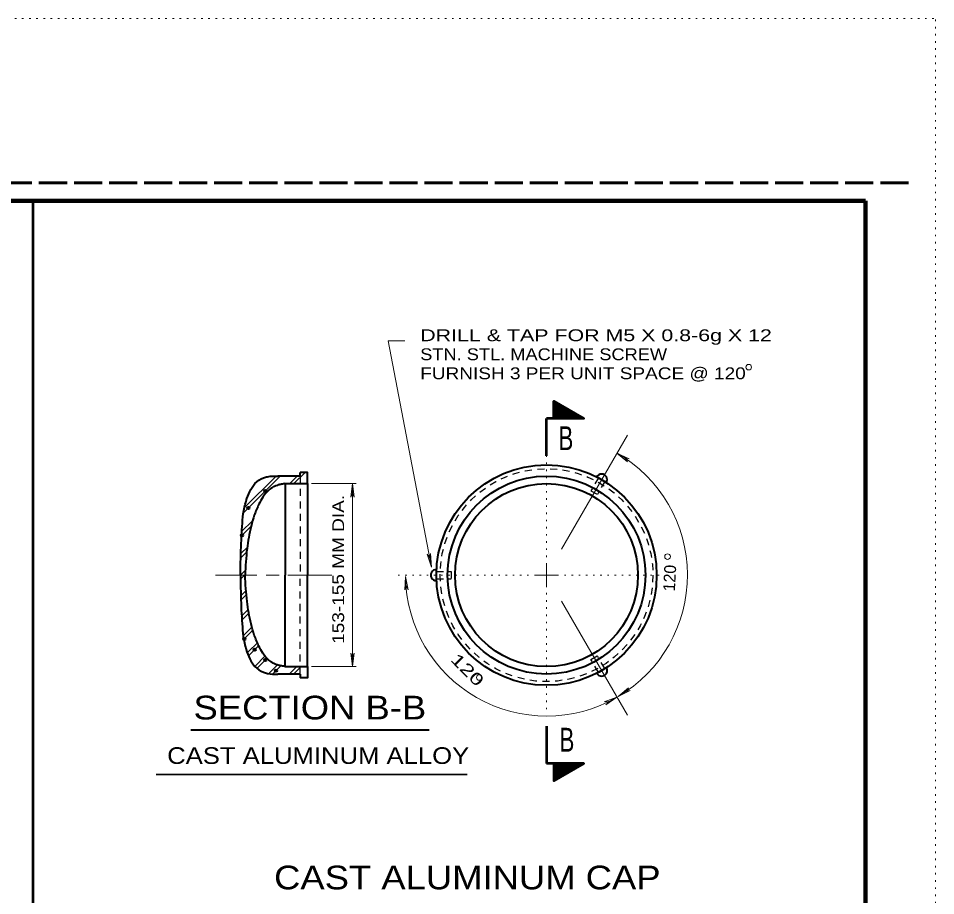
# Model space of a CAD drawing. Extents: x 312583 to 312854, y 144419 to 144597.
# Drawn here: x 312794.6 to 312853.5, y 144540.5 to 144596.8 of the extents above; entities that cross this region are included whole.
import ezdxf
from ezdxf.enums import TextEntityAlignment as Align

# ---------------------------------------------------------------- set-up
doc = ezdxf.new("R2010")
doc.units = 0
doc.header["$LTSCALE"] = 0.3
doc.header["$PDMODE"] = 32
doc.header["$PDSIZE"] = 0.15
for name, pattern in [('DOTTED', [1.5, 0.3, -1.2]), ('LONG_DASHED', [7.5, 6, -1.5]), ('SHORT_DASHED', [2.7, 1.5, -1.2])]:
    doc.linetypes.add(name, pattern=pattern)
for name, color, linetype, lineweight in [('1', 7, 'Continuous', 40), ('2', 7, 'Continuous', 13), ('62', 7, 'DOTTED', 13), ('63', 7, 'LONG_DASHED', 60)]:
    doc.layers.add(name, color=color, linetype=linetype, lineweight=lineweight)

msp = doc.modelspace()

# ---------------------------------------------------------------- linework, layer by layer
at = {"layer": '1', "lineweight": 158}
msp.add_line((312849, 144423.1446), (312849, 144585.0846), dxfattribs=at)
at = {"layer": '1', "lineweight": 13}
for p, q in [((312833.7137, 144570.0532), (312829.4971, 144562.7468)), ((312809.1267, 144565.1082), (312811.4344, 144567.4235)), ((312812.0401, 144566.9405), (312812.5231, 144567.4235)), ((312812.3084, 144566.9405), (312813.0291, 144567.6612)), ((312812.7147, 144567.6152), (312812.7607, 144567.6612)), ((312809.1651, 144565.4225), (312811.1277, 144567.3852)), ((312808.9581, 144563.8662), (312809.6481, 144564.5485)), ((312808.9504, 144563.5825), (312809.5791, 144564.2112)), ((312808.9197, 144562.4708), (312809.3031, 144562.8465)), ((312808.9121, 144562.1872), (312809.2571, 144562.5322)), ((312808.8814, 144561.0755), (312809.1957, 144561.3898)), ((312808.8891, 144560.8072), (312809.1804, 144561.1062)), ((312808.9044, 144559.7415), (312809.2417, 144560.0788)), ((312808.9121, 144559.4732), (312809.2647, 144559.8258)), ((312833.7137, 144552.0902), (312829.4971, 144559.3965)), ((312808.9351, 144558.4152), (312809.4027, 144558.8828)), ((312808.9504, 144558.1545), (312809.4411, 144558.6528)), ((312809.0577, 144557.1808), (312809.5944, 144557.7175)), ((312809.0807, 144556.9355), (312809.6634, 144557.5182)), ((312809.3721, 144556.1458), (312809.9701, 144556.7362)), ((312809.4641, 144555.9618), (312810.0467, 144556.5445)), ((312809.8167, 144555.2335), (312810.4761, 144555.8928)), ((312809.9394, 144555.0802), (312810.6141, 144555.7625)), ((312810.7137, 144554.7735), (312811.2811, 144555.3408)), ((312810.9744, 144554.7658), (312811.4957, 144555.2795)), ((312812.0324, 144554.7352), (312812.5001, 144555.2028)), ((312812.3007, 144554.7352), (312812.7684, 144555.2028)), ((312813.1364, 144554.4822), (312813.1901, 144554.5435))]:
    msp.add_line(p, q, dxfattribs=at)
at = {"layer": '1'}
for p, q in [((312812.7147, 144567.4235), (312811.2734, 144567.4235)), ((312812.7147, 144567.4235), (312812.7147, 144567.6612)), ((312811.7564, 144566.9405), (312811.7564, 144561.0755)), ((312813.1901, 144566.9405), (312813.1901, 144561.0755)), ((312831.7511, 144567.3698), (312832.3721, 144567.0172)), ((312811.7564, 144555.2028), (312811.7564, 144561.0755)), ((312813.1901, 144555.2028), (312813.1901, 144561.0755)), ((312821.4547, 144560.7152), (312821.4547, 144561.4282)), ((312832.3721, 144555.1338), (312831.7511, 144554.7735)), ((312812.7147, 144554.7198), (312811.2734, 144554.7198)), ((312812.7147, 144554.7198), (312812.7147, 144554.4822))]:
    msp.add_line(p, q, dxfattribs=at)
at = {"layer": '1', "linetype": 'SHORT_DASHED', "lineweight": 25}
for p, q in [((312812.7147, 144567.4235), (312812.7147, 144561.0755)), ((312831.8507, 144567.3162), (312831.3754, 144566.4805)), ((312832.2647, 144567.0785), (312831.7894, 144566.2428)), ((312831.7894, 144566.2428), (312831.3754, 144566.4805)), ((312812.7147, 144554.7198), (312812.7147, 144561.0755)), ((312821.4547, 144561.3132), (312822.4131, 144561.3132)), ((312822.4131, 144561.3132), (312822.4131, 144560.8302)), ((312821.4547, 144560.8302), (312822.4131, 144560.8302)), ((312831.3754, 144555.6628), (312831.7894, 144555.9005)), ((312831.8584, 144554.8348), (312831.3754, 144555.6628)), ((312832.2647, 144555.0725), (312831.7894, 144555.9005))]:
    msp.add_line(p, q, dxfattribs=at)
at = {"layer": '1', "lineweight": 158}
msp.add_lwpolyline([(312616.5, 144423.1446), (312616.5, 144585.0846), (312849, 144585.0846)], dxfattribs=at)
at = {"layer": '1', "lineweight": 53}
msp.add_lwpolyline([(312849, 144468.4167), (312795.5728, 144468.4167), (312795.5728, 144585.0846)], dxfattribs=at)
at = {"layer": '1'}
for points in [[(312811.7564, 144566.9405), (312813.1901, 144566.9405), (312813.1901, 144567.6612), (312812.7147, 144567.6612)], [(312811.7564, 144555.2028), (312813.1901, 144555.2028), (312813.1901, 144554.4822), (312812.7147, 144554.4822)]]:
    msp.add_lwpolyline(points, dxfattribs=at)
for radius in [7.0687, 6.3499, 5.8708]:
    msp.add_circle((312828.5253, 144561.0717), radius, dxfattribs=at)
at = {"layer": '1', "linetype": 'SHORT_DASHED', "lineweight": 25}
msp.add_circle((312828.5253, 144561.0717), 6.8291, dxfattribs=at)
at = {"layer": '1'}
for centre, start, end in [((312832.0603, 144567.1964), 329.52448, 150.47552), ((312821.4537, 144561.0707), 89.52448, 270.47552), ((312832.062, 144554.9479), 209.52448, 30.47552)]:
    msp.add_arc(centre, 0.3575, start, end, dxfattribs=at)
for points in [[(312808.8814, 144561.0755), (312808.9044, 144562.4325), (312808.9887, 144564.1882), (312809.0654, 144565.0085), (312809.2494, 144565.8365), (312809.4871, 144566.4345), (312809.8091, 144566.9405), (312810.3611, 144567.3085), (312810.6217, 144567.3852), (312811.2734, 144567.4235)], [(312811.7564, 144566.9405), (312811.5264, 144566.9022), (312811.3117, 144566.8562), (312810.9897, 144566.7258), (312810.6984, 144566.5188), (312810.3151, 144566.0818), (312810.0697, 144565.6218), (312809.7707, 144564.9242), (312809.5714, 144564.1958), (312809.4104, 144563.4828), (312809.3031, 144562.7698), (312809.1804, 144561.0602)], [(312808.8814, 144561.0755), (312808.9044, 144559.7108), (312808.9887, 144557.9552), (312809.0654, 144557.1425), (312809.2494, 144556.3068), (312809.4871, 144555.7088), (312809.8091, 144555.2105), (312810.3611, 144554.8425), (312810.6217, 144554.7658), (312811.2734, 144554.7198)], [(312811.7564, 144555.2028), (312811.5264, 144555.2488), (312811.3117, 144555.2872), (312810.9897, 144555.4175), (312810.6984, 144555.6245), (312810.3151, 144556.0615), (312810.0697, 144556.5215), (312809.7707, 144557.2192), (312809.5714, 144557.9475), (312809.4104, 144558.6605), (312809.3031, 144559.3812), (312809.1804, 144561.0602)]]:
    msp.add_spline(points, degree=3, dxfattribs=at)
for p in [(312810.4761, 144566.4652), (312809.3951, 144565.3765), (312808.9887, 144563.6208), (312809.1267, 144556.9738), (312809.8014, 144556.2992), (312810.4761, 144555.6245), (312811.1584, 144554.9422)]:
    msp.add_point(p, dxfattribs=at)
at = {"layer": '2'}
for p, q in [((312819.4231, 144576.1022), (312818.3574, 144576.1022)), ((312821.1404, 144561.5892), (312818.3574, 144576.1022)), ((312833.0467, 144568.9032), (312833.7214, 144568.3435)), ((312833.0467, 144568.9032), (312833.8364, 144568.5275)), ((312833.7214, 144568.3435), (312833.5451, 144568.5888)), ((312833.8364, 144568.5275), (312833.5451, 144568.5888)), ((312813.4354, 144566.9405), (312816.3104, 144566.9405)), ((312816.0651, 144566.9405), (312815.9577, 144566.0742)), ((312816.0651, 144555.2028), (312816.0651, 144566.9405)), ((312816.0651, 144566.9405), (312816.1724, 144566.0742)), ((312815.9577, 144566.0742), (312816.0651, 144566.3502)), ((312816.1724, 144566.0742), (312816.0651, 144566.3502)), ((312820.8721, 144562.4248), (312821.0254, 144562.1718)), ((312821.1404, 144561.5892), (312820.8721, 144562.4248)), ((312821.0791, 144562.4632), (312821.0254, 144562.1718)), ((312821.1404, 144561.5892), (312821.0791, 144562.4632)), ((312828.5234, 144561.0755), (312828.5234, 144561.8422)), ((312807.2791, 144561.0755), (312809.9317, 144561.0755)), ((312810.5221, 144561.0755), (312811.3731, 144561.0755)), ((312811.9327, 144561.0755), (312814.7387, 144561.0755)), ((312819.4844, 144560.9912), (312819.4307, 144560.1172)), ((312819.4844, 144560.9912), (312819.6377, 144560.1325)), ((312828.5234, 144561.0755), (312827.7567, 144561.0755)), ((312828.5234, 144561.0755), (312827.7567, 144561.0755)), ((312828.5234, 144561.0755), (312828.5234, 144560.3088)), ((312828.5234, 144561.0755), (312829.2901, 144561.0755)), ((312819.4307, 144560.1172), (312819.5151, 144560.4008)), ((312819.6377, 144560.1325), (312819.5151, 144560.4008)), ((312815.9577, 144556.0692), (312816.0651, 144555.7932)), ((312816.0651, 144555.2028), (312815.9577, 144556.0692)), ((312816.1724, 144556.0692), (312816.0651, 144555.7932)), ((312816.0651, 144555.2028), (312816.1724, 144556.0692)), ((312813.4354, 144555.2028), (312816.3104, 144555.2028)), ((312833.1157, 144553.2785), (312833.7827, 144553.8458)), ((312833.1157, 144553.2785), (312833.8977, 144553.6695)), ((312833.7827, 144553.8458), (312833.6141, 144553.6082)), ((312833.8977, 144553.6695), (312833.6141, 144553.6082)), ((312833.0467, 144553.2402), (312832.2264, 144552.9335)), ((312832.2264, 144552.9335), (312832.5254, 144552.9718)), ((312833.0467, 144553.2402), (312832.3261, 144552.7495)), ((312832.3261, 144552.7495), (312832.5254, 144552.9718))]:
    msp.add_line(p, q, dxfattribs=at)
at = {"layer": '2', "lineweight": 35}
for p, q in [((312828.9987, 144572.1998), (312829.0141, 144572.2152)), ((312828.9987, 144572.1538), (312829.0371, 144572.2075)), ((312828.9987, 144572.1002), (312829.0524, 144572.1922)), ((312828.9987, 144572.0542), (312829.0754, 144572.1768)), ((312828.9987, 144572.0005), (312829.0984, 144572.1692)), ((312828.9987, 144571.9622), (312829.1137, 144572.1538)), ((312828.9987, 144571.9085), (312829.1367, 144572.1462)), ((312828.9987, 144571.8625), (312829.1597, 144572.1308)), ((312828.9987, 144571.8165), (312829.1751, 144572.1232)), ((312828.9987, 144571.7705), (312829.2057, 144572.1078)), ((312828.9987, 144571.7168), (312829.2211, 144572.1002)), ((312828.9987, 144571.6708), (312829.2441, 144572.0848)), ((312828.9987, 144571.6248), (312829.2671, 144572.0772)), ((312828.9987, 144571.5712), (312829.2824, 144572.0618)), ((312828.9987, 144571.5252), (312829.3054, 144572.0542)), ((312828.9987, 144571.4792), (312829.3207, 144572.0388)), ((312828.9987, 144571.4255), (312829.3437, 144572.0235)), ((312828.9987, 144571.3795), (312829.3667, 144572.0158)), ((312828.9987, 144571.3335), (312829.3821, 144572.0005)), ((312828.9987, 144571.2875), (312829.4051, 144571.9852)), ((312828.9987, 144571.2338), (312829.4281, 144571.9775)), ((312828.9987, 144571.1955), (312829.4434, 144571.9622)), ((312828.9987, 144571.1418), (312829.4741, 144571.9545)), ((312829.0141, 144571.1188), (312829.4894, 144571.9392)), ((312829.0447, 144571.1188), (312829.5124, 144571.9315)), ((312829.0754, 144571.1188), (312829.5354, 144571.9162)), ((312829.0984, 144571.1188), (312829.5507, 144571.9085)), ((312829.1291, 144571.1188), (312829.5737, 144571.8932)), ((312829.1521, 144571.1265), (312829.5967, 144571.8855)), ((312829.1827, 144571.1265), (312829.6121, 144571.8702)), ((312829.2057, 144571.1188), (312829.6351, 144571.8625)), ((312829.2364, 144571.1188), (312829.6581, 144571.8472)), ((312829.2671, 144571.1188), (312829.6734, 144571.8318)), ((312829.2901, 144571.1188), (312829.6964, 144571.8242)), ((312829.3207, 144571.1188), (312829.7194, 144571.8088)), ((312829.3514, 144571.1188), (312829.7424, 144571.7935)), ((312829.3744, 144571.1188), (312829.7577, 144571.7858)), ((312829.4051, 144571.1265), (312829.7807, 144571.7705)), ((312829.4357, 144571.1188), (312829.8037, 144571.7628)), ((312829.4587, 144571.1188), (312829.8191, 144571.7475)), ((312829.4817, 144571.1188), (312829.8421, 144571.7398)), ((312829.5124, 144571.1188), (312829.8651, 144571.7245)), ((312829.5431, 144571.1188), (312829.8804, 144571.7168)), ((312829.5737, 144571.1188), (312829.9034, 144571.7015)), ((312829.5967, 144571.1188), (312829.9264, 144571.6938)), ((312829.6274, 144571.1188), (312829.9417, 144571.6785)), ((312829.6504, 144571.1265), (312829.9724, 144571.6708)), ((312829.6811, 144571.1188), (312829.9877, 144571.6555)), ((312829.7041, 144571.1188), (312830.0107, 144571.6402)), ((312829.7347, 144571.1188), (312830.0337, 144571.6325)), ((312829.7654, 144571.1188), (312830.0491, 144571.6172)), ((312829.7884, 144571.1188), (312830.0721, 144571.6095)), ((312829.8191, 144571.1188), (312830.0951, 144571.5942)), ((312829.8497, 144571.1188), (312830.1104, 144571.5865)), ((312829.8727, 144571.1188), (312830.1334, 144571.5712)), ((312829.9034, 144571.1188), (312830.1564, 144571.5635)), ((312829.9341, 144571.1188), (312830.1717, 144571.5482)), ((312829.9571, 144571.1188), (312830.1947, 144571.5405)), ((312829.9801, 144571.1188), (312830.2177, 144571.5252)), ((312830.0107, 144571.1188), (312830.2407, 144571.5175)), ((312830.0414, 144571.1188), (312830.2561, 144571.5022)), ((312830.0721, 144571.1188), (312830.2791, 144571.4868)), ((312830.0951, 144571.1188), (312830.3021, 144571.4792)), ((312830.1257, 144571.1188), (312830.3174, 144571.4638)), ((312830.1487, 144571.1188), (312830.3404, 144571.4485)), ((312830.1794, 144571.1188), (312830.3634, 144571.4408)), ((312830.2024, 144571.1188), (312830.3787, 144571.4255)), ((312830.2331, 144571.1188), (312830.4017, 144571.4178)), ((312830.2637, 144571.1188), (312830.4247, 144571.4025)), ((312830.2867, 144571.1188), (312830.4401, 144571.3948)), ((312830.3174, 144571.1188), (312830.4707, 144571.3795)), ((312830.3404, 144571.1188), (312830.4861, 144571.3718)), ((312830.3711, 144571.1188), (312830.5091, 144571.3565)), ((312830.4017, 144571.1188), (312830.5321, 144571.3488)), ((312830.4247, 144571.1188), (312830.5474, 144571.3335)), ((312830.4554, 144571.1188), (312830.5704, 144571.3258)), ((312830.4784, 144571.1188), (312830.5934, 144571.3105)), ((312830.5091, 144571.1188), (312830.6087, 144571.2952)), ((312830.5397, 144571.1188), (312830.6317, 144571.2875)), ((312830.5704, 144571.1188), (312830.6547, 144571.2722)), ((312830.5934, 144571.1188), (312830.6701, 144571.2568)), ((312830.6241, 144571.1188), (312830.6931, 144571.2492)), ((312830.6471, 144571.1188), (312830.7161, 144571.2338)), ((312830.6701, 144571.1188), (312830.7391, 144571.2262)), ((312830.7007, 144571.1188), (312830.7544, 144571.2108)), ((312830.7314, 144571.1188), (312830.7774, 144571.2032)), ((312830.7621, 144571.1188), (312830.8004, 144571.1878)), ((312830.7851, 144571.1188), (312830.8157, 144571.1802)), ((312830.8157, 144571.1188), (312830.8387, 144571.1648)), ((312830.8387, 144571.1188), (312830.8617, 144571.1572)), ((312830.8694, 144571.1188), (312830.8771, 144571.1418)), ((312830.9001, 144571.1188), (312830.9001, 144571.1342)), ((312828.9987, 144548.9622), (312829.4741, 144548.1495)), ((312828.9987, 144548.9085), (312829.4434, 144548.1418)), ((312828.9987, 144548.8702), (312829.4281, 144548.1265)), ((312828.9987, 144548.8165), (312829.4051, 144548.1188)), ((312828.9987, 144548.7705), (312829.3821, 144548.1035)), ((312828.9987, 144548.7245), (312829.3667, 144548.0882)), ((312828.9987, 144548.6785), (312829.3437, 144548.0805)), ((312828.9987, 144548.6248), (312829.3207, 144548.0652)), ((312828.9987, 144548.5788), (312829.3054, 144548.0498)), ((312829.0141, 144548.9852), (312829.4894, 144548.1648)), ((312829.0447, 144548.9852), (312829.5124, 144548.1725)), ((312829.0754, 144548.9852), (312829.5354, 144548.1878)), ((312829.0984, 144548.9852), (312829.5507, 144548.1955)), ((312829.1291, 144548.9852), (312829.5737, 144548.2108)), ((312829.1521, 144548.9775), (312829.5967, 144548.2185)), ((312829.1827, 144548.9775), (312829.6121, 144548.2338)), ((312829.2057, 144548.9852), (312829.6351, 144548.2415)), ((312829.2364, 144548.9852), (312829.6581, 144548.2568)), ((312829.2671, 144548.9852), (312829.6734, 144548.2722)), ((312829.2901, 144548.9852), (312829.6964, 144548.2798)), ((312829.3207, 144548.9852), (312829.7194, 144548.2952)), ((312829.3514, 144548.9852), (312829.7424, 144548.3105)), ((312829.3744, 144548.9852), (312829.7577, 144548.3182)), ((312829.4051, 144548.9775), (312829.7807, 144548.3335)), ((312829.4357, 144548.9852), (312829.8037, 144548.3412)), ((312829.4587, 144548.9852), (312829.8191, 144548.3565)), ((312829.4817, 144548.9852), (312829.8421, 144548.3642)), ((312829.5124, 144548.9852), (312829.8651, 144548.3795)), ((312829.5431, 144548.9852), (312829.8804, 144548.3872)), ((312829.5737, 144548.9852), (312829.9034, 144548.4025)), ((312829.5967, 144548.9852), (312829.9264, 144548.4102)), ((312829.6274, 144548.9852), (312829.9417, 144548.4255)), ((312829.6504, 144548.9775), (312829.9724, 144548.4332)), ((312829.6811, 144548.9852), (312829.9877, 144548.4485)), ((312829.7041, 144548.9852), (312830.0107, 144548.4638)), ((312829.7347, 144548.9852), (312830.0337, 144548.4715)), ((312829.7654, 144548.9852), (312830.0491, 144548.4868)), ((312829.7884, 144548.9852), (312830.0721, 144548.4945)), ((312829.8191, 144548.9852), (312830.0951, 144548.5098)), ((312829.8497, 144548.9852), (312830.1104, 144548.5175)), ((312829.8727, 144548.9852), (312830.1334, 144548.5328)), ((312829.9034, 144548.9852), (312830.1564, 144548.5405)), ((312829.9341, 144548.9852), (312830.1717, 144548.5558)), ((312829.9571, 144548.9852), (312830.1947, 144548.5635)), ((312829.9801, 144548.9852), (312830.2177, 144548.5788)), ((312830.0107, 144548.9852), (312830.2407, 144548.5865)), ((312830.0414, 144548.9852), (312830.2561, 144548.6018)), ((312830.0721, 144548.9852), (312830.2791, 144548.6172)), ((312830.0951, 144548.9852), (312830.3021, 144548.6248)), ((312830.1257, 144548.9852), (312830.3174, 144548.6402)), ((312830.1487, 144548.9852), (312830.3404, 144548.6555)), ((312830.1794, 144548.9852), (312830.3634, 144548.6632)), ((312830.2024, 144548.9852), (312830.3787, 144548.6785)), ((312830.2331, 144548.9852), (312830.4017, 144548.6862)), ((312830.2637, 144548.9852), (312830.4247, 144548.7015)), ((312830.2867, 144548.9852), (312830.4401, 144548.7092)), ((312830.3174, 144548.9852), (312830.4707, 144548.7245)), ((312830.3404, 144548.9852), (312830.4861, 144548.7322)), ((312830.3711, 144548.9852), (312830.5091, 144548.7475)), ((312830.4017, 144548.9852), (312830.5321, 144548.7552)), ((312830.4247, 144548.9852), (312830.5474, 144548.7705)), ((312830.4554, 144548.9852), (312830.5704, 144548.7782)), ((312830.4784, 144548.9852), (312830.5934, 144548.7935)), ((312830.5091, 144548.9852), (312830.6087, 144548.8088)), ((312830.5397, 144548.9852), (312830.6317, 144548.8165)), ((312830.5704, 144548.9852), (312830.6547, 144548.8318)), ((312830.5934, 144548.9852), (312830.6701, 144548.8472)), ((312830.6241, 144548.9852), (312830.6931, 144548.8548)), ((312830.6471, 144548.9852), (312830.7161, 144548.8702)), ((312830.6701, 144548.9852), (312830.7391, 144548.8778)), ((312830.7007, 144548.9852), (312830.7544, 144548.8932)), ((312830.7314, 144548.9852), (312830.7774, 144548.9008)), ((312830.7621, 144548.9852), (312830.8004, 144548.9162)), ((312830.7851, 144548.9852), (312830.8157, 144548.9238)), ((312830.8157, 144548.9852), (312830.8387, 144548.9392)), ((312830.8387, 144548.9852), (312830.8617, 144548.9468)), ((312830.8694, 144548.9852), (312830.8771, 144548.9622)), ((312830.9001, 144548.9852), (312830.9001, 144548.9698)), ((312803.4671, 144548.2722), (312823.4383, 144548.2722)), ((312828.9987, 144548.5328), (312829.2824, 144548.0422)), ((312828.9987, 144548.4792), (312829.2671, 144548.0268)), ((312828.9987, 144548.4332), (312829.2441, 144548.0192)), ((312828.9987, 144548.3872), (312829.2211, 144548.0038)), ((312828.9987, 144548.3335), (312829.2057, 144547.9962)), ((312828.9987, 144548.2875), (312829.1751, 144547.9808)), ((312828.9987, 144548.2415), (312829.1597, 144547.9732)), ((312828.9987, 144548.1955), (312829.1367, 144547.9578)), ((312828.9987, 144548.1418), (312829.1137, 144547.9502)), ((312828.9987, 144548.1035), (312829.0984, 144547.9348)), ((312828.9987, 144548.0498), (312829.0754, 144547.9272)), ((312828.9987, 144548.0038), (312829.0524, 144547.9118)), ((312828.9987, 144547.9502), (312829.0371, 144547.8965)), ((312828.9987, 144547.9042), (312829.0141, 144547.8888))]:
    msp.add_line(p, q, dxfattribs=at)
at = {"layer": '2', "lineweight": 53}
for p, q in [((312828.5234, 144568.7268), (312828.5234, 144571.1188)), ((312828.9987, 144571.1188), (312828.5234, 144571.1188)), ((312828.5234, 144551.3772), (312828.5234, 144548.9852)), ((312828.9987, 144548.9852), (312828.5234, 144548.9852))]:
    msp.add_line(p, q, dxfattribs=at)
at = {"layer": '2', "linetype": 'DOTTED'}
for p, q in [((312828.5234, 144562.2255), (312828.5234, 144569.8922)), ((312827.3734, 144561.0755), (312818.6641, 144561.0755)), ((312829.6734, 144561.0755), (312835.9064, 144561.0755)), ((312828.5234, 144559.9255), (312828.5234, 144552.3738))]:
    msp.add_line(p, q, dxfattribs=at)
at = {"layer": '2', "lineweight": 40}
msp.add_line((312805.6976, 144551.1453), (312820.9949, 144551.1453), dxfattribs=at)
at = {"layer": '2', "lineweight": 53}
for points in [[(312828.9987, 144571.1188), (312828.9987, 144572.2305), (312830.9154, 144571.1188)], [(312828.9987, 144548.9852), (312828.9987, 144547.8735), (312830.9154, 144548.9852)]]:
    msp.add_lwpolyline(points, close=True, dxfattribs=at)
at = {"layer": '2'}
for centre in [(312841.5007, 144574.4101), (312836.2921, 144562.2593), (312824.2109, 144554.5052)]:
    msp.add_circle(centre, 0.1797, dxfattribs=at)
for start, end in [(300.50993, 59.99393), (180.50993, 299.99393)]:
    msp.add_arc((312828.5253, 144561.0717), 9.0451, start, end, dxfattribs=at)
at = {"layer": '62'}
msp.add_line((312601.2, 144596.7846), (312853.5, 144596.7846), dxfattribs=at)
msp.add_lwpolyline([(312601.2, 144418.5846), (312853.5, 144418.5846), (312853.5, 144596.7846)], dxfattribs=at)
at = {"layer": '63'}
msp.add_line((312851.75, 144586.2246), (312583.526, 144586.2246), dxfattribs=at)

# ---------------------------------------------------------------- texts
at = {"layer": '2'}
for s, height, width, p in [('DRILL & TAP FOR M5 X 0.8-6g X 12', 0.76, 1.35, (312820.4194, 144576.0773)), ('STN. STL. MACHINE SCREW', 0.76, 1.15, (312820.4194, 144574.8573)), ('FURNISH 3 PER UNIT SPACE @ 120', 0.76, 1.2, (312820.4194, 144573.6373)), ('SECTION B-B', 1.52, 1.15, (312805.8679, 144551.8157)), ('CAST ALUMINUM ALLOY', 1.07, 1.15, (312804.179, 144548.9611)), ('CAST ALUMINUM CAP', 1.52, 1.15, (312811.039, 144540.9155))]:
    msp.add_text(s, height=height, dxfattribs=dict(at, width=width)).set_placement(p)
at = {"layer": '2', "width": 0.7}
for p in [(312829.7654, 144569.0872), (312829.8344, 144549.7442)]:
    msp.add_text('B', height=1.533, dxfattribs=at).set_placement(p, align=Align.CENTER)
at = {"layer": '2'}
for s, rotation, width, p in [('153-155 MM DIA.', 90, 1.2, (312815.5351, 144556.6624)), ('120', 315, 1.45, (312822.3138, 144555.6011))]:
    msp.add_text(s, height=0.76, rotation=rotation, dxfattribs=dict(at, width=width)).set_placement(p)
msp.add_text('120', height=0.76, rotation=87, dxfattribs=at).set_placement((312836.7634, 144560.017))

doc.saveas('drawing.dxf')
